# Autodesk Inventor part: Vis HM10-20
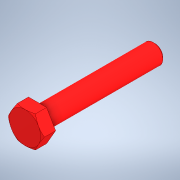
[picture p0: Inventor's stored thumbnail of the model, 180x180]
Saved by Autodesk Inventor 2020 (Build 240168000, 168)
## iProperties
Created: 2003-05
Part Number: Vis HM10-20
Material: Générique
Document SubType Name: Modeling
Designer: Bruno
Density: 1 g/cm^3
Appearance: Par défaut
Author: Bruno
Sending System: SolidWorks 2011
Last Author: frederic
Last Saved: 2012-02-20
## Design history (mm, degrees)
feature "Chanfrein1"
node "Solide1"
